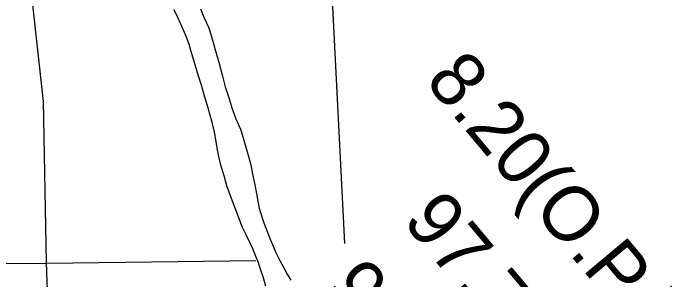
# Model space of a CAD drawing. Extents: x 22866 to 28196, y 1324810 to 1328105.
# Drawn here: x 24260.5 to 24428, y 1327231 to 1327299.2 of the extents above; entities that cross this region are included whole.
import ezdxf

# ---------------------------------------------------------------- set-up
doc = ezdxf.new("R2010")
doc.units = 0
for name, color, linetype in [('Level 5', 7, 'Continuous'), ('Level 58', 7, 'Continuous'), ('Level 9', 7, 'Continuous')]:
    doc.layers.add(name, color=color, linetype=linetype)

msp = doc.modelspace()

# ---------------------------------------------------------------- linework, layer by layer
at = {"layer": 'Level 5'}
for points in [[(24270.01, 1327205.96), (24268.97, 1327235.56), (24268.26, 1327276.64), (24263.79, 1327316.9)], [(24270.01, 1327205.96), (24268.97, 1327235.56), (24268.26, 1327276.64), (24263.79, 1327316.9)], [(24345.18, 1327240.34), (24341.78, 1327307.69)], [(24345.18, 1327240.34), (24341.78, 1327307.69)], [(24322.45, 1327235.86), (24269.11, 1327235.16)], [(24322.45, 1327235.86), (24269.11, 1327235.16)], [(24269.11, 1327235.16), (24181.69, 1327234.71)], [(24269.11, 1327235.16), (24181.69, 1327234.71)]]:
    msp.add_lwpolyline(points, dxfattribs=at)
at = {"layer": 'Level 9'}
for points in [[(24325, 1327229.44), (24324.33, 1327231.83), (24323.77, 1327233.52), (24323.15, 1327235.41), (24322.42, 1327237.23), (24321.7, 1327238.95), (24320.94, 1327240.57), (24319.98, 1327242.49), (24319.05, 1327244.37), (24318.15, 1327246.92), (24317.15, 1327249.37), (24316.25, 1327251.79), (24315.66, 1327253.45), (24315.07, 1327255.1), (24314.37, 1327257.59), (24313.53, 1327260.34), (24313.1, 1327262.2), (24313.03, 1327262.6), (24312.7, 1327264.26), (24312.34, 1327266.39), (24311.87, 1327268.81), (24311.44, 1327271.04), (24310.66, 1327273.69), (24310.21, 1327275.25), (24309.72, 1327276.87), (24309.26, 1327278.37), (24308.59, 1327280.79), (24307.79, 1327283.11), (24306.95, 1327285.99), (24305.87, 1327289.67), (24305.44, 1327291.33), (24304.54, 1327293.68), (24303.41, 1327296.26), (24302.48, 1327298.25), (24301.62, 1327300.1)], [(24325, 1327229.44), (24324.33, 1327231.83), (24323.77, 1327233.52), (24323.15, 1327235.41), (24322.42, 1327237.23), (24321.7, 1327238.95), (24320.94, 1327240.57), (24319.98, 1327242.49), (24319.05, 1327244.37), (24318.15, 1327246.92), (24317.15, 1327249.37), (24316.25, 1327251.79), (24315.66, 1327253.45), (24315.07, 1327255.1), (24314.37, 1327257.59), (24313.53, 1327260.34), (24313.1, 1327262.2), (24313.03, 1327262.6), (24312.7, 1327264.26), (24312.34, 1327266.39), (24311.87, 1327268.81), (24311.44, 1327271.04), (24310.66, 1327273.69), (24310.21, 1327275.25), (24309.72, 1327276.87), (24309.26, 1327278.37), (24308.59, 1327280.79), (24307.79, 1327283.11), (24306.95, 1327285.99), (24305.87, 1327289.67), (24305.44, 1327291.33), (24304.54, 1327293.68), (24303.41, 1327296.26), (24302.48, 1327298.25), (24301.62, 1327300.1)], [(24308.33, 1327300.37), (24309.22, 1327298.22), (24310.46, 1327295.44), (24311.37, 1327292.32), (24312.15, 1327289.6), (24312.99, 1327286.65), (24313.94, 1327283.07), (24314.65, 1327280.41), (24315.55, 1327277.66), (24316.33, 1327275.01), (24317.33, 1327272.2), (24318.53, 1327269.58), (24319.09, 1327267.96), (24320.64, 1327262.55), (24321.17, 1327260.4), (24321.64, 1327258.04), (24322.18, 1327255.28), (24322.64, 1327253.12), (24322.97, 1327251.1), (24323.33, 1327249.34), (24324.07, 1327246.92), (24324.55, 1327245.56), (24325.35, 1327243.4), (24326.14, 1327241.45), (24326.87, 1327239.63), (24327.49, 1327238.17)], [(24308.33, 1327300.37), (24309.22, 1327298.22), (24310.46, 1327295.44), (24311.37, 1327292.32), (24312.15, 1327289.6), (24312.99, 1327286.65), (24313.94, 1327283.07), (24314.65, 1327280.41), (24315.55, 1327277.66), (24316.33, 1327275.01), (24317.33, 1327272.2), (24318.53, 1327269.58), (24319.09, 1327267.96), (24320.64, 1327262.55), (24321.17, 1327260.4), (24321.64, 1327258.04), (24322.18, 1327255.28), (24322.64, 1327253.12), (24322.97, 1327251.1), (24323.33, 1327249.34), (24324.07, 1327246.92), (24324.55, 1327245.56), (24325.35, 1327243.4), (24326.14, 1327241.45), (24326.87, 1327239.63), (24327.49, 1327238.17)], [(24327.49, 1327238.17), (24328.69, 1327235.76), (24329.54, 1327234.24), (24330.47, 1327232.49), (24331.39, 1327230.97)], [(24327.49, 1327238.17), (24328.69, 1327235.76), (24329.54, 1327234.24), (24330.47, 1327232.49), (24331.39, 1327230.97)]]:
    msp.add_lwpolyline(points, dxfattribs=at)

# ---------------------------------------------------------------- texts
at = {"layer": 'Level 58'}
for s, p in [('8.20(O.P.)', (24365.41, 1327281.82)), ('8.20(O.P.)', (24365.41, 1327281.82)), ('97.76', (24359.7, 1327246)), ('97.76', (24359.7, 1327246)), ('97.06', (24339.74, 1327228.67)), ('97.06', (24339.74, 1327228.67))]:
    msp.add_text(s, height=14.044, rotation=310, dxfattribs=at).set_placement(p)

doc.saveas('drawing.dxf')
